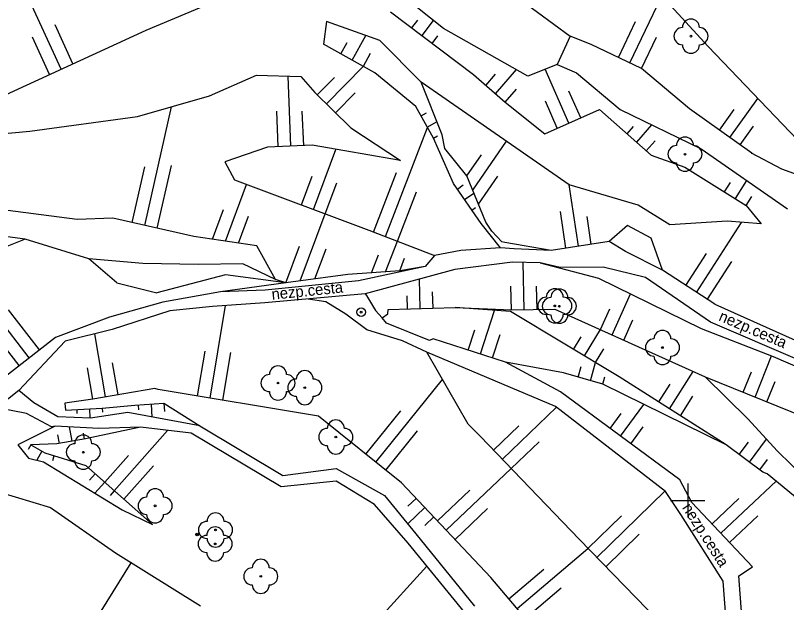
# Model space of a CAD drawing. Extents: x -639440 to -639026, y -1138850 to -1138262.
# Drawn here: x -639239.4 to -639194.21, y -1138655.97 to -1138621.6 of the extents above; entities that cross this region are included whole.
import ezdxf

# ---------------------------------------------------------------- set-up
doc = ezdxf.new("R2010")
doc.units = 0
for name, color, linetype in [('Vrstva 11', 7, 'Continuous'), ('Vrstva 14', 7, 'Continuous'), ('Vrstva 15', 7, 'Continuous'), ('Vrstva 20', 7, 'Continuous'), ('Vrstva 22', 7, 'Continuous'), ('Vrstva 25', 7, 'Continuous'), ('Vrstva 40', 7, 'Continuous'), ('Vrstva 61', 7, 'Continuous')]:
    doc.layers.add(name, color=color, linetype=linetype)

msp = doc.modelspace()

# ---------------------------------------------------------------- linework, layer by layer
at = {"layer": 'Vrstva 11'}
for p, q in [((-639214.38, -1138628.59), (-639215.62, -1138625.5)), ((-639214.24, -1138629.38), (-639214.38, -1138628.59)), ((-639212.94, -1138630.99), (-639214.24, -1138629.38)), ((-639211.83, -1138633.69), (-639212.94, -1138630.99)), ((-639211.48, -1138634.23), (-639211.83, -1138633.69)), ((-639210.89, -1138634.86), (-639211.48, -1138634.23)), ((-639210.72, -1138634.9), (-639210.89, -1138634.86)), ((-639208, -1138635.35), (-639210.72, -1138634.9)), ((-639203.64, -1138635.42), (-639204.61, -1138634.84)), ((-639201.48, -1138636.52), (-639203.64, -1138635.42)), ((-639215.38, -1138636.3), (-639219.3, -1138637.13)), ((-639210.27, -1138636.05), (-639213.64, -1138636.47)), ((-639208.65, -1138636.08), (-639210.27, -1138636.05)), ((-639207.47, -1138636.36), (-639208.65, -1138636.08)), ((-639213.64, -1138636.47), (-639218.9, -1138637.89)), ((-639204.96, -1138636.34), (-639207.47, -1138636.36)), ((-639202.48, -1138636.93), (-639204.96, -1138636.34)), ((-639219.3, -1138637.13), (-639224.76, -1138637.69)), ((-639198.66, -1138639.56), (-639202.48, -1138636.93)), ((-639233.45, -1138637.25), (-639231.12, -1138637.84)), ((-639224.76, -1138637.69), (-639227.38, -1138637.78)), ((-639227.38, -1138637.78), (-639230.75, -1138638.39)), ((-639218.9, -1138637.89), (-639224.79, -1138638.43)), ((-639218.9, -1138637.89), (-639218.82, -1138638)), ((-639218.82, -1138638), (-639218.3, -1138638.87)), ((-639230.75, -1138638.39), (-639233.89, -1138639.26)), ((-639224.79, -1138638.43), (-639227.85, -1138638.64)), ((-639221.2, -1138638.36), (-639222.25, -1138638.2)), ((-639220.03, -1138639.09), (-639221.2, -1138638.36)), ((-639230.34, -1138638.9), (-639233.72, -1138639.98)), ((-639227.85, -1138638.64), (-639230.34, -1138638.9)), ((-639218.3, -1138638.87), (-639217.91, -1138639.31)), ((-639233.89, -1138639.26), (-639237.05, -1138640.45)), ((-639218.81, -1138640), (-639220.03, -1138639.09)), ((-639217.65, -1138639.62), (-639217.91, -1138639.31)), ((-639215.13, -1138640.62), (-639217.65, -1138639.62)), ((-639193.43, -1138641.79), (-639198.66, -1138639.56)), ((-639233.72, -1138639.98), (-639236.49, -1138640.66)), ((-639216.72, -1138640.65), (-639218.81, -1138640)), ((-639237.05, -1138640.45), (-639240.45, -1138643.08)), ((-639236.49, -1138640.66), (-639239.19, -1138643.56)), ((-639215.28, -1138641.32), (-639216.72, -1138640.65)), ((-639214.91, -1138640.53), (-639215.13, -1138640.62)), ((-639210.67, -1138641.89), (-639214.91, -1138640.53)), ((-639207.75, -1138644.49), (-639215.28, -1138641.32)), ((-639207.45, -1138643.63), (-639210.67, -1138641.89)), ((-639196.48, -1138645.22), (-639198.98, -1138642.76)), ((-639239.19, -1138643.56), (-639240.5, -1138644.56)), ((-639238.32, -1138644.28), (-639239.19, -1138643.56)), ((-639200.47, -1138648.78), (-639207.45, -1138643.63)), ((-639236.91, -1138645.09), (-639238.32, -1138644.28)), ((-639238.75, -1138644.9), (-639240.5, -1138644.56)), ((-639237.28, -1138645.69), (-639238.75, -1138644.9)), ((-639232.81, -1138644.85), (-639235, -1138645.18)), ((-639228.6, -1138645.63), (-639232.81, -1138644.85)), ((-639201.3, -1138649.47), (-639207.75, -1138644.49)), ((-639235, -1138645.18), (-639236.91, -1138645.09)), ((-639194.74, -1138647.11), (-639196.48, -1138645.22)), ((-639237.06, -1138645.65), (-639237.28, -1138645.69)), ((-639234.5, -1138645.78), (-639237.06, -1138645.65)), ((-639232.06, -1138645.71), (-639234.5, -1138645.78)), ((-639229.1, -1138646.05), (-639232.06, -1138645.71)), ((-639228.6, -1138645.63), (-639223.73, -1138648.53)), ((-639223.83, -1138649.2), (-639229.1, -1138646.05)), ((-639191.57, -1138650.23), (-639194.74, -1138647.11)), ((-639223.73, -1138648.53), (-639220.6, -1138648.13)), ((-639220.6, -1138648.13), (-639217.76, -1138649.7)), ((-639220.6, -1138648.86), (-639223.83, -1138649.2)), ((-639218.35, -1138650.24), (-639220.6, -1138648.86)), ((-639199.75, -1138650.11), (-639200.47, -1138648.78)), ((-639217.76, -1138649.7), (-639215.93, -1138651.95)), ((-639200.41, -1138650.81), (-639201.3, -1138649.47)), ((-639216.38, -1138652.5), (-639218.35, -1138650.24)), ((-639196.2, -1138653.89), (-639199.75, -1138650.11)), ((-639197.92, -1138654.72), (-639200.41, -1138650.81)), ((-639215.93, -1138651.95), (-639212.5, -1138656.19)), ((-639213.08, -1138656.54), (-639216.38, -1138652.5)), ((-639197, -1138654.41), (-639196.2, -1138653.89)), ((-639196.82, -1138656.76), (-639197, -1138654.41)), ((-639197.64, -1138658.27), (-639197.92, -1138654.72))]:
    msp.add_line(p, q, dxfattribs=at)
at = {"layer": 'Vrstva 14'}
for p, q in [((-639231.73, -1138622.45), (-639223.66, -1138619.06)), ((-639198.81, -1138623.41), (-639202.48, -1138619.4)), ((-639214.31, -1138622.36), (-639216.71, -1138620.45)), ((-639209.76, -1138620.68), (-639206.89, -1138622.81)), ((-639217.41, -1138621.38), (-639212.56, -1138625.05)), ((-639221.16, -1138621.95), (-639221.35, -1138623.27)), ((-639218.05, -1138623.07), (-639221.16, -1138621.95)), ((-639240.77, -1138626.61), (-639231.73, -1138622.45)), ((-639209.36, -1138625.15), (-639214.31, -1138622.36)), ((-639215.62, -1138625.5), (-639218.05, -1138623.07)), ((-639206.89, -1138622.81), (-639207.65, -1138624.46)), ((-639205.66, -1138623.29), (-639206.89, -1138622.81)), ((-639218.33, -1138624.95), (-639221.35, -1138623.27)), ((-639202.71, -1138624.7), (-639205.66, -1138623.29)), ((-639192.7, -1138629.79), (-639198.81, -1138623.41)), ((-639207.65, -1138624.46), (-639209.36, -1138625.15)), ((-639207.65, -1138624.46), (-639206.51, -1138624.96)), ((-639215.94, -1138626.92), (-639218.33, -1138624.95)), ((-639206.51, -1138624.96), (-639203.95, -1138627.11)), ((-639199.89, -1138627.06), (-639202.71, -1138624.7)), ((-639228.03, -1138626.3), (-639225.27, -1138625.1)), ((-639225.27, -1138625.1), (-639222.67, -1138625.18)), ((-639222.67, -1138625.18), (-639221.85, -1138626.11)), ((-639212.56, -1138625.05), (-639210.69, -1138626.67)), ((-639206.94, -1138631.51), (-639215.62, -1138625.5)), ((-639232.25, -1138627.52), (-639228.03, -1138626.3)), ((-639221.85, -1138626.11), (-639219.75, -1138628.17)), ((-639210.69, -1138626.67), (-639208.38, -1138628.52)), ((-639214.9, -1138628.79), (-639215.94, -1138626.92)), ((-639208.38, -1138628.52), (-639205.17, -1138627.11)), ((-639205.17, -1138627.11), (-639202.14, -1138629.77)), ((-639203.95, -1138627.11), (-639199.22, -1138629.4)), ((-639196.24, -1138629.66), (-639199.89, -1138627.06)), ((-639238.55, -1138628.38), (-639232.25, -1138627.52)), ((-639219.75, -1138628.17), (-639216.83, -1138630.09)), ((-639246.01, -1138629.03), (-639238.55, -1138628.38)), ((-639213.72, -1138631.44), (-639214.9, -1138628.79)), ((-639224.62, -1138629.31), (-639227.12, -1138630.17)), ((-639222.01, -1138629.2), (-639224.62, -1138629.31)), ((-639216.83, -1138630.09), (-639222.01, -1138629.2)), ((-639199.22, -1138629.4), (-639194.15, -1138632.91)), ((-639202.14, -1138629.77), (-639200.17, -1138630.47)), ((-639194.49, -1138630.6), (-639196.27, -1138629.66)), ((-639196.27, -1138629.66), (-639196.24, -1138629.66)), ((-639227.12, -1138630.17), (-639226.55, -1138631.23)), ((-639200.17, -1138630.47), (-639196.57, -1138632.72)), ((-639193.07, -1138631.11), (-639194.49, -1138630.6)), ((-639226.55, -1138631.23), (-639218.69, -1138634.17)), ((-639212.1, -1138633.78), (-639213.72, -1138631.44)), ((-639202.9, -1138632.7), (-639206.94, -1138631.51)), ((-639201.04, -1138633.85), (-639202.9, -1138632.7)), ((-639235.77, -1138633.54), (-639240.46, -1138632.94)), ((-639196.57, -1138632.72), (-639195.69, -1138633.8)), ((-639233.68, -1138633.47), (-639235.77, -1138633.54)), ((-639228.94, -1138634.54), (-639233.68, -1138633.47)), ((-639210.97, -1138635.21), (-639212.1, -1138633.78)), ((-639203.53, -1138633.89), (-639204.61, -1138634.84)), ((-639202.14, -1138634.64), (-639203.53, -1138633.89)), ((-639197.69, -1138633.65), (-639201.04, -1138633.85)), ((-639195.69, -1138633.8), (-639197.69, -1138633.65)), ((-639238.83, -1138634.7), (-639242.49, -1138634.22)), ((-639218.69, -1138634.17), (-639214.84, -1138635.65)), ((-639238.83, -1138634.7), (-639240.32, -1138635.28)), ((-639235.1, -1138635.84), (-639238.83, -1138634.7)), ((-639225.26, -1138635.08), (-639228.94, -1138634.54)), ((-639204.61, -1138634.84), (-639208, -1138635.35)), ((-639201.48, -1138636.52), (-639202.14, -1138634.64)), ((-639224.16, -1138637.06), (-639225.26, -1138635.08)), ((-639213.3, -1138635.36), (-639214.84, -1138635.65)), ((-639210.97, -1138635.21), (-639213.3, -1138635.36)), ((-639210.17, -1138635.26), (-639210.97, -1138635.21)), ((-639208, -1138635.35), (-639210.17, -1138635.26)), ((-639233.45, -1138637.25), (-639235.1, -1138635.84)), ((-639231.93, -1138636.12), (-639235.1, -1138635.84)), ((-639214.84, -1138635.65), (-639215.38, -1138636.3)), ((-639228.66, -1138636.17), (-639231.93, -1138636.12)), ((-639226.07, -1138636.14), (-639228.66, -1138636.17)), ((-639224.16, -1138637.06), (-639226.07, -1138636.14)), ((-639215.38, -1138636.3), (-639216.88, -1138636.55)), ((-639208.65, -1138636.08), (-639205.23, -1138636.98)), ((-639219.92, -1138636.76), (-639223.55, -1138637.26)), ((-639216.88, -1138636.55), (-639219.92, -1138636.76)), ((-639198.41, -1138638.5), (-639201.48, -1138636.52)), ((-639227.09, -1138636.79), (-639231.12, -1138637.84)), ((-639223.55, -1138637.26), (-639227.09, -1138636.79)), ((-639223.55, -1138637.26), (-639224.16, -1138637.06)), ((-639205.23, -1138636.98), (-639199.22, -1138639.92)), ((-639223.55, -1138637.26), (-639227.38, -1138637.78)), ((-639198.41, -1138638.5), (-639192.88, -1138640.99)), ((-639217.58, -1138639.06), (-639217.56, -1138638.81)), ((-639217.56, -1138638.81), (-639213.62, -1138638.69)), ((-639213.62, -1138638.69), (-639210.33, -1138638.84)), ((-639210.38, -1138638.94), (-639213.62, -1138638.69)), ((-639204.01, -1138642.75), (-639210.38, -1138638.94)), ((-639210.33, -1138638.84), (-639207.78, -1138638.79)), ((-639207.78, -1138638.79), (-639198.98, -1138642.76)), ((-639217.91, -1138639.31), (-639217.58, -1138639.06)), ((-639199.22, -1138639.92), (-639195, -1138641.56)), ((-639212.87, -1138645.52), (-639215.28, -1138641.32)), ((-639195, -1138641.56), (-639189.45, -1138644)), ((-639207.28, -1138642.53), (-639210.67, -1138641.89)), ((-639204.98, -1138643.19), (-639207.28, -1138642.53)), ((-639197.74, -1138646.74), (-639204.01, -1138642.75)), ((-639198.98, -1138642.76), (-639192.66, -1138645.31)), ((-639231.23, -1138643.44), (-639234.86, -1138644.06)), ((-639231.04, -1138643.49), (-639231.23, -1138643.44)), ((-639221.64, -1138645.05), (-639231.04, -1138643.49)), ((-639197.74, -1138646.74), (-639204.98, -1138643.19)), ((-639234.86, -1138644.06), (-639236.51, -1138644.29)), ((-639236.51, -1138644.29), (-639236.46, -1138644.7)), ((-639234.31, -1138644.59), (-639232.4, -1138644.42)), ((-639232.4, -1138644.42), (-639230.7, -1138644.3)), ((-639230.7, -1138644.3), (-639228.6, -1138645.63)), ((-639236.46, -1138644.7), (-639234.31, -1138644.59)), ((-639216.78, -1138648.96), (-639221.64, -1138645.05)), ((-639237.06, -1138645.65), (-639238.82, -1138646.52)), ((-639232.06, -1138645.71), (-639235.29, -1138646.38)), ((-639212.15, -1138646.24), (-639212.87, -1138645.52)), ((-639206.37, -1138652.27), (-639212.15, -1138646.24)), ((-639238.82, -1138646.52), (-639239.26, -1138646.74)), ((-639236.98, -1138646.68), (-639238.49, -1138646.74)), ((-639235.29, -1138646.38), (-639236.98, -1138646.68)), ((-639239.26, -1138646.74), (-639238.63, -1138647.51)), ((-639238.49, -1138646.74), (-639237.68, -1138647.21)), ((-639195.59, -1138648.34), (-639197.74, -1138646.74)), ((-639238.63, -1138647.51), (-639237.75, -1138647.73)), ((-639237.68, -1138647.21), (-639235.28, -1138647.94)), ((-639237.75, -1138647.73), (-639233.14, -1138650.55)), ((-639235.28, -1138647.94), (-639231.37, -1138651.4)), ((-639195.35, -1138648.43), (-639195.59, -1138648.34)), ((-639191.85, -1138651.33), (-639195.35, -1138648.43)), ((-639211.53, -1138654.5), (-639216.78, -1138648.96)), ((-639241.43, -1138649.17), (-639237.35, -1138650.4)), ((-639237.35, -1138650.4), (-639233.54, -1138653.07)), ((-639233.14, -1138650.55), (-639231.37, -1138651.4)), ((-639200.71, -1138658.05), (-639206.37, -1138652.27)), ((-639233.54, -1138653.07), (-639228.55, -1138656.16)), ((-639206.61, -1138660.31), (-639211.53, -1138654.5))]:
    msp.add_line(p, q, dxfattribs=at)
at = {"layer": 'Vrstva 15'}
for p, q in [((-639236.709, -1138624.741), (-639238.762, -1138620.28)), ((-639203.387, -1138624.377), (-639201.513, -1138620.457)), ((-639236.028, -1138624.428), (-639237.076, -1138622.151)), ((-639216.163, -1138622.324), (-639215.823, -1138621.875)), ((-639215.565, -1138622.776), (-639214.897, -1138621.893)), ((-639204.063, -1138624.053), (-639203.061, -1138621.957)), ((-639219.665, -1138624.207), (-639218.868, -1138622.775)), ((-639237.391, -1138625.055), (-639238.396, -1138622.871)), ((-639220.32, -1138623.843), (-639219.952, -1138623.18)), ((-639214.967, -1138623.229), (-639214.638, -1138622.794)), ((-639202.71, -1138624.7), (-639201.838, -1138622.877)), ((-639219.009, -1138624.572), (-639218.581, -1138623.802)), ((-639221.171, -1138626.776), (-639219.009, -1138624.572)), ((-639211.257, -1138626.179), (-639210.036, -1138624.769)), ((-639206.959, -1138627.896), (-639208.345, -1138624.74)), ((-639223.25, -1138629.252), (-639223.423, -1138625.157)), ((-639221.706, -1138626.251), (-639220.697, -1138625.223)), ((-639211.824, -1138625.688), (-639211.263, -1138625.041)), ((-639210.69, -1138626.67), (-639210.029, -1138625.907)), ((-639220.635, -1138627.301), (-639219.482, -1138626.126)), ((-639206.272, -1138627.594), (-639206.961, -1138626.027)), ((-639207.646, -1138628.197), (-639208.343, -1138626.609)), ((-639197.532, -1138628.74), (-639195.9, -1138626.449)), ((-639231.816, -1138633.891), (-639230.247, -1138626.941)), ((-639223.999, -1138629.284), (-639224.087, -1138627.209)), ((-639222.501, -1138629.221), (-639222.586, -1138627.2)), ((-639215.629, -1138627.479), (-639215.301, -1138627.296)), ((-639198.143, -1138628.304), (-639197.286, -1138627.101)), ((-639217.714, -1138634.545), (-639215.256, -1138628.15)), ((-639215.265, -1138628.134), (-639214.691, -1138627.815)), ((-639203.554, -1138628.529), (-639203.176, -1138628.099)), ((-639202.99, -1138629.024), (-639202.097, -1138628.007)), ((-639196.921, -1138629.175), (-639196.147, -1138628.087)), ((-639214.9, -1138628.79), (-639214.655, -1138628.653)), ((-639212.6, -1138631.817), (-639210.622, -1138628.96)), ((-639202.426, -1138629.519), (-639201.912, -1138628.932)), ((-639221.939, -1138632.955), (-639220.624, -1138629.438)), ((-639212.94, -1138630.99), (-639212.09, -1138629.762)), ((-639232.547, -1138633.726), (-639231.808, -1138630.452)), ((-639231.084, -1138634.056), (-639230.254, -1138630.38)), ((-639218.415, -1138634.276), (-639217.073, -1138630.786)), ((-639222.641, -1138632.692), (-639222.009, -1138631)), ((-639212.26, -1138632.643), (-639211.133, -1138631.015)), ((-639197.206, -1138632.323), (-639196.539, -1138631.256)), ((-639227.089, -1138634.812), (-639225.848, -1138631.493)), ((-639221.237, -1138633.217), (-639220.554, -1138631.392)), ((-639213.499, -1138631.759), (-639213.159, -1138631.523)), ((-639206.399, -1138635.109), (-639206.94, -1138631.51)), ((-639197.842, -1138631.925), (-639197.499, -1138631.377)), ((-639217.014, -1138634.814), (-639215.903, -1138631.923)), ((-639213.072, -1138632.375), (-639212.526, -1138631.997)), ((-639196.57, -1138632.72), (-639196.246, -1138632.202)), ((-639227.848, -1138634.7), (-639227.199, -1138632.965)), ((-639212.646, -1138632.992), (-639212.44, -1138632.85)), ((-639207.141, -1138635.221), (-639207.464, -1138633.072)), ((-639226.33, -1138634.923), (-639225.737, -1138633.339)), ((-639222.705, -1138637.144), (-639221.237, -1138633.217)), ((-639205.657, -1138634.998), (-639205.902, -1138633.371)), ((-639199.48, -1138637.81), (-639196.839, -1138633.714)), ((-639217.705, -1138636.607), (-639217.015, -1138634.814)), ((-639223.549, -1138637.26), (-639222.744, -1138635.107)), ((-639221.861, -1138637.027), (-639221.197, -1138635.254)), ((-639218.53, -1138636.664), (-639218.123, -1138635.604)), ((-639216.879, -1138636.55), (-639216.597, -1138635.816)), ((-639200.111, -1138637.403), (-639198.9, -1138635.527)), ((-639209.58, -1138638.825), (-639209.634, -1138636.062)), ((-639198.85, -1138638.216), (-639197.419, -1138635.997)), ((-639238.586, -1138641.638), (-639242.467, -1138636.622)), ((-639215.674, -1138638.753), (-639215.726, -1138637.033)), ((-639210.329, -1138638.84), (-639210.357, -1138637.452)), ((-639208.83, -1138638.811), (-639208.857, -1138637.443)), ((-639216.423, -1138638.775), (-639216.447, -1138638.005)), ((-639214.924, -1138638.73), (-639214.953, -1138637.781)), ((-639204.433, -1138640.3), (-639203.35, -1138637.9)), ((-639227.979, -1138643.998), (-639227.081, -1138638.587)), ((-639237.993, -1138641.179), (-639239.806, -1138638.835)), ((-639212.147, -1138641.416), (-639211.329, -1138638.867)), ((-639205.116, -1138639.992), (-639204.57, -1138638.781)), ((-639239.179, -1138642.097), (-639241.246, -1138639.425)), ((-639203.749, -1138640.608), (-639203.212, -1138639.419)), ((-639234.121, -1138643.934), (-639234.753, -1138640.234)), ((-639212.861, -1138641.187), (-639212.479, -1138639.997)), ((-639211.433, -1138641.645), (-639210.997, -1138640.286)), ((-639206.041, -1138641.535), (-639205.117, -1138639.991)), ((-639206.684, -1138641.15), (-639206.245, -1138640.416)), ((-639228.719, -1138643.875), (-639228.285, -1138641.258)), ((-639205.397, -1138641.92), (-639204.913, -1138641.111)), ((-639227.239, -1138644.121), (-639226.776, -1138641.328)), ((-639196.056, -1138643.94), (-639195.083, -1138641.528)), ((-639233.381, -1138643.807), (-639233.702, -1138641.931)), ((-639206.422, -1138642.776), (-639206.242, -1138642.149)), ((-639205.701, -1138642.983), (-639205.397, -1138641.921)), ((-639234.86, -1138644.06), (-639235.171, -1138642.236)), ((-639201.058, -1138644.628), (-639199.671, -1138642.448)), ((-639196.752, -1138643.659), (-639196.267, -1138642.458)), ((-639218.273, -1138647.759), (-639214.369, -1138642.907)), ((-639204.98, -1138643.19), (-639204.856, -1138642.754)), ((-639195.361, -1138644.22), (-639194.878, -1138643.023)), ((-639201.691, -1138644.226), (-639201.026, -1138643.181)), ((-639200.425, -1138645.031), (-639199.703, -1138643.896)), ((-639232.196, -1138644.406), (-639232.176, -1138644.688)), ((-639231.447, -1138644.353), (-639231.394, -1138645.112)), ((-639230.7, -1138644.3), (-639230.666, -1138644.777)), ((-639203.933, -1138646.225), (-639202.567, -1138644.373)), ((-639235.808, -1138644.667), (-639235.795, -1138644.905)), ((-639235.059, -1138644.628), (-639235.03, -1138645.179)), ((-639234.31, -1138644.59), (-639234.298, -1138644.831)), ((-639218.857, -1138647.289), (-639216.814, -1138644.749)), ((-639210.861, -1138647.585), (-639207.685, -1138644.54)), ((-639204.537, -1138645.779), (-639203.894, -1138644.908)), ((-639236.079, -1138646.52), (-639236.226, -1138645.692)), ((-639211.38, -1138647.043), (-639209.901, -1138645.625)), ((-639203.33, -1138646.67), (-639202.606, -1138645.689)), ((-639236.817, -1138646.651), (-639236.906, -1138646.152)), ((-639235.34, -1138646.389), (-639235.399, -1138646.06)), ((-639233.604, -1138649.423), (-639230.479, -1138645.892)), ((-639217.688, -1138648.229), (-639215.829, -1138645.917)), ((-639210.342, -1138648.126), (-639208.713, -1138646.565)), ((-639196.98, -1138647.306), (-639196.439, -1138646.579)), ((-639196.378, -1138647.754), (-639195.381, -1138646.414)), ((-639238.49, -1138646.74), (-639238.65, -1138647.015)), ((-639237.841, -1138647.116), (-639238.141, -1138647.632)), ((-639237.141, -1138647.374), (-639237.234, -1138647.681)), ((-639234.166, -1138648.926), (-639232.777, -1138647.356)), ((-639195.776, -1138648.201), (-639195.32, -1138647.588)), ((-639233.043, -1138649.92), (-639231.306, -1138647.958)), ((-639234.728, -1138648.428), (-639235.058, -1138648.802)), ((-639214.15, -1138651.735), (-639210.342, -1138648.126)), ((-639234.166, -1138648.925), (-639234.739, -1138649.572)), ((-639198.063, -1138651.907), (-639194.825, -1138648.865)), ((-639233.605, -1138649.422), (-639233.847, -1138649.696)), ((-639214.666, -1138651.191), (-639212.763, -1138649.388)), ((-639215.917, -1138649.871), (-639216.398, -1138650.327)), ((-639205.32, -1138653.342), (-639201.337, -1138649.442)), ((-639198.576, -1138651.36), (-639197.001, -1138649.881)), ((-639215.401, -1138650.415), (-639216.405, -1138651.366)), ((-639213.634, -1138652.28), (-639211.728, -1138650.474)), ((-639214.885, -1138650.959), (-639215.408, -1138651.454)), ((-639205.845, -1138652.806), (-639203.89, -1138650.893)), ((-639197.549, -1138652.453), (-639195.896, -1138650.9)), ((-639204.795, -1138653.878), (-639202.849, -1138651.973)), ((-639209.99, -1138656.318), (-639205.844, -1138652.807)), ((-639236.256, -1138659.494), (-639232.616, -1138653.642)), ((-639222.47, -1138661.708), (-639215.288, -1138653.837)), ((-639210.475, -1138655.746), (-639208.423, -1138654.008)), ((-639209.506, -1138656.89), (-639207.412, -1138655.117))]:
    msp.add_line(p, q, dxfattribs=at)
at = {"layer": 'Vrstva 20'}
for radius in [0.075, 0.0204]:
    msp.add_circle((-639228.75, -1138651.99), radius, dxfattribs=at)
at = {"layer": 'Vrstva 22'}
for centre in [(-639199.81, -1138622.81), (-639200.16, -1138629.72), (-639207.79, -1138638.6), (-639207.52, -1138638.62), (-639201.48, -1138641.04), (-639224.01, -1138643.12), (-639222.44, -1138643.39), (-639220.62, -1138646.28), (-639235.42, -1138647.17), (-639231.21, -1138650.31), (-639227.67, -1138651.72), (-639227.69, -1138652.54), (-639225.02, -1138654.44)]:
    msp.add_circle(centre, 0.05, dxfattribs=at)
for centre, start, end in [((-639199.81, -1138622.31), 0, 180), ((-639200.31, -1138622.81), 90, 270), ((-639199.31, -1138622.81), 270, 90), ((-639199.81, -1138623.31), 180, 0), ((-639200.16, -1138629.22), 0, 180), ((-639200.66, -1138629.72), 90, 270), ((-639199.66, -1138629.72), 270, 90), ((-639200.16, -1138630.22), 180, 0), ((-639207.79, -1138638.1), 0, 180), ((-639207.52, -1138638.12), 0, 180), ((-639208.29, -1138638.6), 90, 270), ((-639208.02, -1138638.62), 90, 270), ((-639207.29, -1138638.6), 270, 90), ((-639207.02, -1138638.62), 270, 90), ((-639207.79, -1138639.1), 180, 0), ((-639207.52, -1138639.12), 180, 0), ((-639201.48, -1138640.54), 0, 180), ((-639201.98, -1138641.04), 90, 270), ((-639200.98, -1138641.04), 270, 90), ((-639201.48, -1138641.54), 180, 0), ((-639224.01, -1138642.62), 0, 180), ((-639224.51, -1138643.12), 90, 270), ((-639223.51, -1138643.12), 270, 90), ((-639222.44, -1138642.89), 0, 180), ((-639222.94, -1138643.39), 90, 270), ((-639221.94, -1138643.39), 270, 90), ((-639224.01, -1138643.62), 180, 0), ((-639222.44, -1138643.89), 180, 0), ((-639220.62, -1138645.78), 0, 180), ((-639221.12, -1138646.28), 90, 270), ((-639220.12, -1138646.28), 270, 90), ((-639235.42, -1138646.67), 0, 180), ((-639235.92, -1138647.17), 90, 270), ((-639234.92, -1138647.17), 270, 90), ((-639220.62, -1138646.78), 180, 0), ((-639235.42, -1138647.67), 180, 0), ((-639231.21, -1138649.81), 0, 180), ((-639231.71, -1138650.31), 90, 270), ((-639230.71, -1138650.31), 270, 90), ((-639227.67, -1138651.22), 0, 180), ((-639231.21, -1138650.81), 180, 0), ((-639228.17, -1138651.72), 90, 270), ((-639227.17, -1138651.72), 270, 90), ((-639227.69, -1138652.04), 0, 180), ((-639228.19, -1138652.54), 90, 270), ((-639227.19, -1138652.54), 270, 90), ((-639227.67, -1138652.22), 180, 0), ((-639227.69, -1138653.04), 180, 0), ((-639225.02, -1138653.94), 0, 180), ((-639225.52, -1138654.44), 90, 270), ((-639224.52, -1138654.44), 270, 90), ((-639225.02, -1138654.94), 180, 0)]:
    msp.add_arc(centre, 0.5, start, end, dxfattribs=at)
at = {"layer": 'Vrstva 25'}
for radius in [0.25, 0.05]:
    msp.add_circle((-639219.14, -1138638.97), radius, dxfattribs=at)
at = {"layer": 'Vrstva 61'}
for p, q in [((-639200, -1138649), (-639200, -1138651)), ((-639201, -1138650), (-639199, -1138650))]:
    msp.add_line(p, q, dxfattribs=at)

# ---------------------------------------------------------------- texts
at = {"layer": 'Vrstva 40'}
for rotation, p in [(5.856, (-639224.355, -1138638.245)), (336.9073, (-639198.233, -1138639.444)), (302.4902, (-639200.35, -1138650.414))]:
    msp.add_text('nezp.cesta', height=0.65, rotation=rotation, dxfattribs=at).set_placement(p)

doc.saveas('drawing.dxf')
